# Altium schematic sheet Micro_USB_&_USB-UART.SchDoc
size 431 x 279 mm; Organization: ORGANIZATION; Address1: ADDRESS 1; Address2: ADDRESS 2; Address3: ADDRESS 3; Address4: ADDRESS 4; Revision: -; SheetNumber: 2; SheetTotal: 4; ENG_APP_DATE: --/--/--; DSN_APP_DATE: --/--/--; CHK_APP_DATE: --/--/--
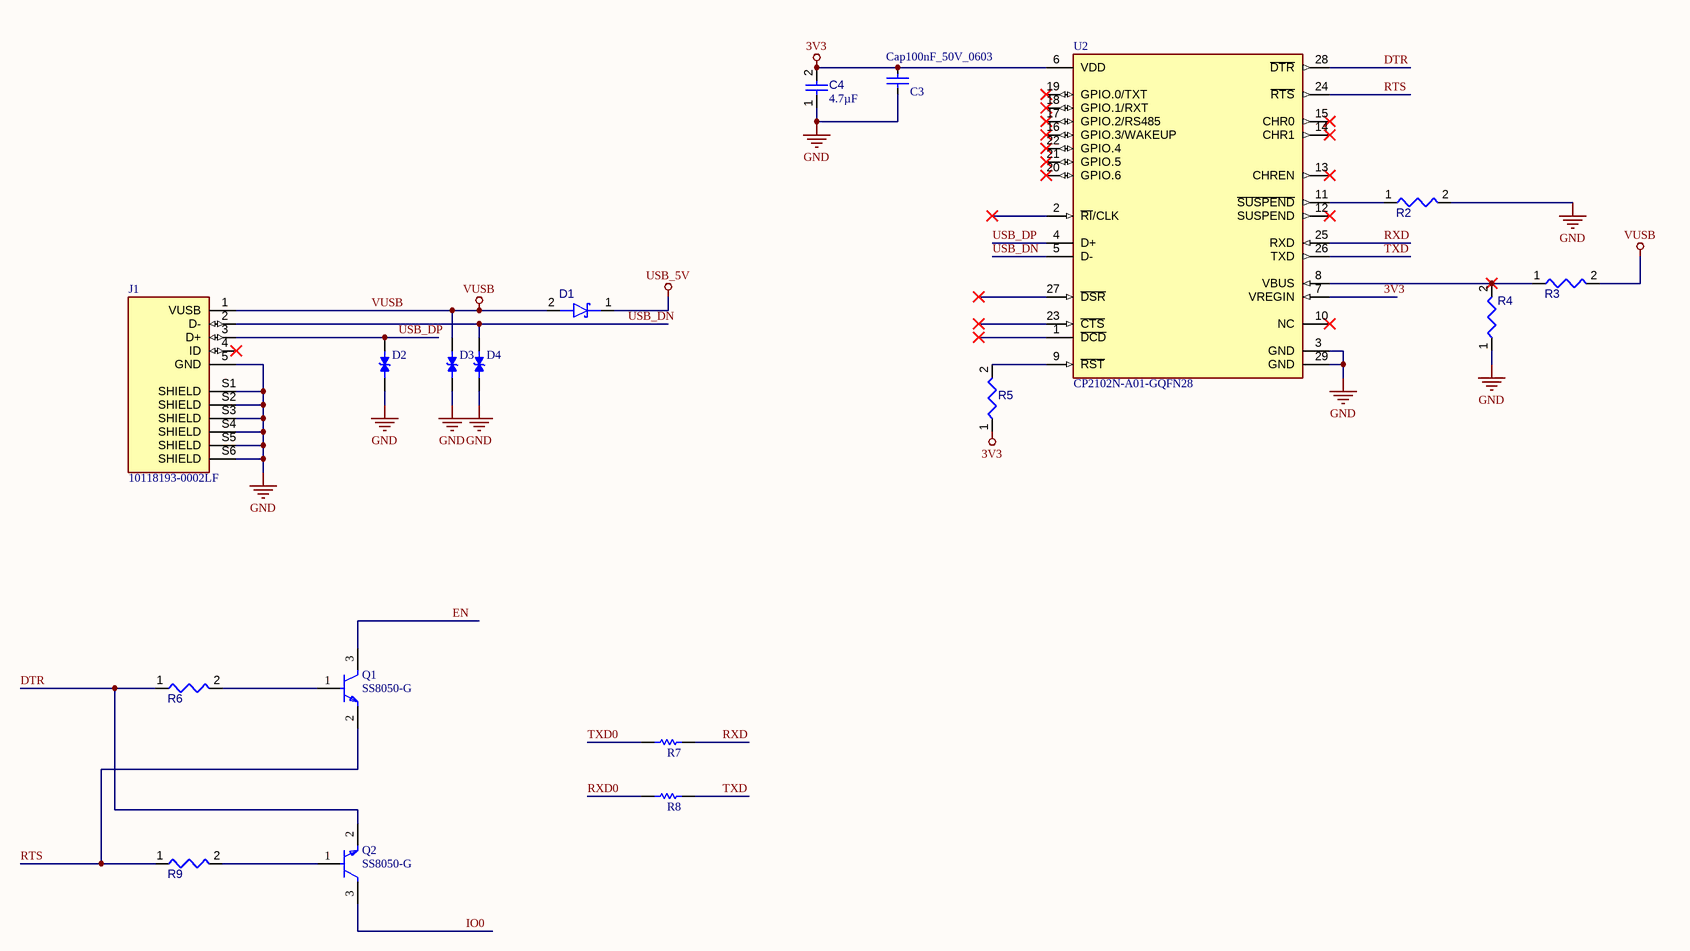
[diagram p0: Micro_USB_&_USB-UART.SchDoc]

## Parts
C3  Cap100nF_50V_0603  [0603C_L]
C4  value 4.7µF  [CAPC0805(2012)145_L]  (hidden comment: Capacitor 4.7µF +/-40% 25V 0805)
D1  RB520CM-30  [ROHM-VMN2-2_V]  (value not drawn)
D2  LESD5D5.0CT1G  [TVS_LESD5D5.0CT1G]  (value not drawn)
D3  LESD5D5.0CT1G  [TVS_LESD5D5.0CT1G]  (value not drawn)
D4  LESD5D5.0CT1G  [TVS_LESD5D5.0CT1G]  (value not drawn)
J1  10118193-0002LF  [AMPHENOL_10118193-0002LF]
Q1  SS8050-G  [FP-SS8050-G-MFG]
Q2  SS8050-G  [FP-SS8050-G-MFG]
R2  Resistor 10K  +/-1 % 0402 63 mW  [RESC0402(1005)_L]  (value not drawn)
R3  MFR-25FBF52-22K1  [RESA60-630X240]  (value not drawn)
R4  Resistor 47K5 +/-1 % 0402 63 mW  [RESC0402(1005)_L]  (value not drawn)
R5  Resistor 2K +/-5 % 0402 63 mW  [RESC0402(1005)_L]  (value not drawn)
R6  Resistor 10K  +/-1 % 0402 63 mW  [RESC0402(1005)_L]  (value not drawn)
R7  Resistor 0R +/- 5% 1206 250 mW  [RESC3216X60X45ML15T20]  (value not drawn)
R8  Resistor 0R +/- 5% 1206 250 mW  [RESC3216X60X45ML15T20]  (value not drawn)
R9  Resistor 10k +/-1% 0805 125 mW  [RESC2013X50X35ML15T15]  (value not drawn)
U2  CP2102N-A01-GQFN28  [FP-CP2102N-A01-GQFN28-MFG]

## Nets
3V3: C3.1 C4.2 R5.1 U2.6(VDD) U2.7(VREGIN)
GND: C3.2 C4.1 D2.1 D3.1 D4.1 J1.5(GND) J1.S1(SHIELD) J1.S2(SHIELD) J1.S3(SHIELD) J1.S4(SHIELD) J1.S5(SHIELD) J1.S6(SHIELD) R2.2 R4.1 U2.3(GND) U2.29(GND)
USB_5V: D1.1(K)
VUSB: D1.2(A) D3.2 J1.1(VUSB) R3.2
DTR: Q2.2(E) R6.1 U2.28(~{DTR})
EN: Q1.3(C)
IO0: Q2.3(C)
RTS: Q1.2(E) R9.1 U2.24(~{RTS})
RXD: R7.2 U2.25(RXD)
RXD0: R8.1
TXD: R8.2 U2.26(TXD)
TXD0: R7.1
USB_DN: D4.2 J1.2(D-) U2.5(D-)
USB_DP: D2.2 J1.3(D+) U2.4(D+)
NetQ1_1: Q1.1(B) R6.2
NetQ2_1: Q2.1(B) R9.2
NetR2_1: R2.1 U2.11(~{SUSPEND})
NetR3_1: R3.1 R4.2 U2.8(VBUS)
NetR5_2: R5.2 U2.9(~{RST})

Not connected (* = marked no-connect by the designer): J1 4(ID)*; U2 1(~{DCD})* 2(~{RI}/CLK)* 10(NC)* 12(SUSPEND)* 13(CHREN)* 14(CHR1)* 15(CHR0)* 16(GPIO.3/WAKEUP)* 17(GPIO.2/RS485)* 18(GPIO.1/RXT)* 19(GPIO.0/TXT)* 20(GPIO.6)* 21(GPIO.5)* 22(GPIO.4)* 23(~{CTS})* 27(~{DSR})*

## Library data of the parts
C3 = CMP-001-00084-1: Ceramic Capacitor, Multilayer, Ceramic, 50V, 80% +Tol, 20% -Tol, Y5V, -82/+22% TC, 0.1uF, Surface Mount, 0603; Manufacturer: Yageo; Manufacturer Part Number: CC0603ZRY5V9BB104; Value: 100nF; Multilayer: Yes
C4 = CMP-001-00080-4: Chip Capacitor, 4.7µF +/-40%, 25V, 0805, Thickness 1.45 mm; Tolerance: 20%
D1 = CMP-004-00028-3: DIODE SCHOTTKY 30V 100MA VMN2M
D2-D4 = LESD5D5.0CT1G: Transient Voltage Suppressors for ESD Protection; MF: Leshan Radio Co.
J1 = 10118193-0002LF: Micro USB 2.0, Input Output Connectors, B TYPE RECEPTACLE with flange; MF: Amphenol ICC (FCI)
Q1 Q2 = CMP-20235-000001-1: NPN TRANSISTOR 1.5A 40V SOT-23 R; Transition Frequency: 100MHz; Max Breakdown Voltage: 25V; Collector Emitter Voltage (VCEO): 400mV; Max Power Dissipation: 300mW
R2 = CMP-009-00149-3: Chip Resistor, 10 kOhms, +/-1 %, 63 mW, -55 to 125 degC, 0402; Tolerance: 1%; Power: 63mW
R3 = CMP-009-00052-4: Axial Resistor, 22.1 KOhm, +/- 1%, 0.25 W, -55 to 155 degC, 2-Pin THD, RoHS, Bulk; Manufacturer: Yageo; Power: 250mW; Voltage Rating: 250V; Value: 22.1k
R4 = CMP-009-00137-3: Chip Resistor, 47,5 kOhms, +/-1 %, 63 mW, -55 to 155 degC, 0402; Tolerance: 1%; Power: 63mW; Value: 47.5k
R5 = CMP-009-00138-3: Chip Resistor, 2 kOhms, +/-5 %, 63 mW, -55 to 155 degC, 0402; Tolerance: 5%; Power: 63mW
R6 = CMP-009-00149-3: Chip Resistor, 10 kOhms, +/-5 %, 63 mW, -55 to 125 degC, 0402; Tolerance: 1%; Power: 63mW
R7 R8 = CMP-009-00002-5: Chip Resistor, 0 Ohm, +/- 5%, 0.25 W, -55 to 155 degC, 1206 (3216 Metric); Power: 250mW; Voltage Rating: 200V; Value: 0
R9 = CMP-009-00018-5: Chip Resistor, 10 KOhm, +/- 5%, 125 mW, -55 to 155 degC, 0805 (2012 Metric); Tolerance: 1%; Power: 125mW; Voltage Rating: 150V
U2 = CMP-08093-000004-1: IC BRIDGE USB TO UART 28QFN; Manufacturer: Silicon Labs; Standoff Height: 0mm; Max Junction Temp: +105°C; Usb Standard: USB 2.0; Number Of Ports: 1; Nominal Supply Current: 195-13700uA; Min Supply Voltage: 1.71V; Max Supply Voltage: 5.25V; Interface: UART,USB,RS-232,RS-485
